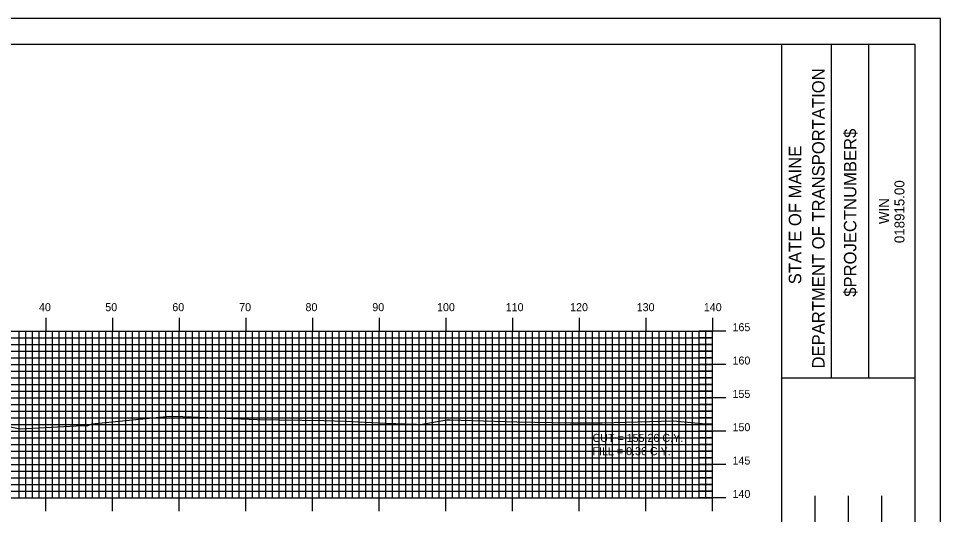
# Model space of a CAD drawing. Extents: x 861045 to 861388, y 364765 to 364985.
# Drawn here: x 861246.8 to 861385.1, y 364910.8 to 364985.2 of the extents above; entities that cross this region are included whole.
import ezdxf

# ---------------------------------------------------------------- set-up
doc = ezdxf.new("R2010")
doc.units = 0
for name, color, linetype in [('BORDER', 7, 'Continuous'), ('D_Text_Standard', 7, 'Continuous'), ('H_V ANNOTATION', 7, 'Continuous'), ('MAJOR', 7, 'Continuous'), ('MINOR', 7, 'Continuous'), ('PLOT BOUNDARY', 7, 'Continuous'), ('S_Roadway_Centerline', 7, 'Continuous')]:
    doc.layers.add(name, color=color, linetype=linetype)

msp = doc.modelspace()

# ---------------------------------------------------------------- linework, layer by layer
at = {"layer": 'BORDER'}
for p, q in [((861361.33, 364771.3), (861361.33, 364981.3)), ((861368.78, 364931.3), (861368.78, 364981.3)), ((861374.37, 364931.3), (861374.37, 364981.3)), ((861361.33, 364931.29), (861381.33, 364931.29)), ((861366.33, 364896.31), (861366.33, 364913.6)), ((861371.33, 364896.31), (861371.33, 364913.6)), ((861376.33, 364896.31), (861376.33, 364913.6))]:
    msp.add_line(p, q, dxfattribs=at)
msp.add_lwpolyline([(861061.33, 364771.3), (861381.33, 364771.3), (861381.33, 364981.3), (861061.33, 364981.3)], close=True, dxfattribs=at)
at = {"layer": 'MAJOR'}
for p, q in [((861250.93, 364940.31), (861250.93, 364938.3)), ((861260.93, 364940.31), (861260.93, 364938.3)), ((861270.93, 364940.31), (861270.93, 364938.3)), ((861280.93, 364940.31), (861280.93, 364938.3)), ((861290.93, 364940.31), (861290.93, 364938.3)), ((861300.93, 364940.31), (861300.93, 364938.3)), ((861310.93, 364940.31), (861310.93, 364938.3)), ((861320.93, 364940.31), (861320.93, 364938.3)), ((861330.93, 364940.31), (861330.93, 364938.3)), ((861340.93, 364940.31), (861340.93, 364938.3)), ((861350.93, 364940.31), (861350.93, 364938.3)), ((861070.93, 364938.3), (861350.93, 364938.3)), ((861070.93, 364938.3), (861350.93, 364938.3)), ((861070.93, 364938.3), (861350.93, 364938.3)), ((861250.93, 364913.3), (861250.93, 364938.3)), ((861250.93, 364913.3), (861250.93, 364938.3)), ((861260.93, 364913.3), (861260.93, 364938.3)), ((861260.93, 364913.3), (861260.93, 364938.3)), ((861270.93, 364913.3), (861270.93, 364938.3)), ((861270.93, 364913.3), (861270.93, 364938.3)), ((861280.93, 364913.3), (861280.93, 364938.3)), ((861280.93, 364913.3), (861280.93, 364938.3)), ((861290.93, 364913.3), (861290.93, 364938.3)), ((861290.93, 364913.3), (861290.93, 364938.3)), ((861300.93, 364913.3), (861300.93, 364938.3)), ((861300.93, 364913.3), (861300.93, 364938.3)), ((861310.93, 364913.3), (861310.93, 364938.3)), ((861310.93, 364913.3), (861310.93, 364938.3)), ((861320.93, 364913.3), (861320.93, 364938.3)), ((861320.93, 364913.3), (861320.93, 364938.3)), ((861330.93, 364913.3), (861330.93, 364938.3)), ((861330.93, 364913.3), (861330.93, 364938.3)), ((861340.93, 364913.3), (861340.93, 364938.3)), ((861340.93, 364913.3), (861340.93, 364938.3)), ((861352.93, 364938.3), (861348.92, 364938.3)), ((861350.93, 364913.3), (861350.93, 364938.3)), ((861350.93, 364913.3), (861350.93, 364938.3)), ((861350.93, 364913.3), (861350.93, 364938.3)), ((861070.93, 364933.3), (861350.93, 364933.3)), ((861070.93, 364933.3), (861350.93, 364933.3)), ((861352.93, 364933.3), (861348.92, 364933.3)), ((861070.93, 364928.3), (861350.93, 364928.3)), ((861070.93, 364928.3), (861350.93, 364928.3)), ((861352.93, 364928.3), (861348.92, 364928.3)), ((861070.93, 364923.3), (861350.93, 364923.3)), ((861070.93, 364923.3), (861350.93, 364923.3)), ((861352.93, 364923.3), (861348.92, 364923.3)), ((861070.93, 364918.3), (861350.93, 364918.3)), ((861070.93, 364918.3), (861350.93, 364918.3)), ((861352.93, 364918.3), (861348.92, 364918.3)), ((861070.93, 364913.3), (861350.93, 364913.3)), ((861070.93, 364913.3), (861350.93, 364913.3)), ((861070.93, 364913.3), (861350.93, 364913.3)), ((861250.93, 364911.3), (861250.93, 364913.3)), ((861260.93, 364911.3), (861260.93, 364913.3)), ((861270.93, 364911.3), (861270.93, 364913.3)), ((861280.93, 364911.3), (861280.93, 364913.3)), ((861290.93, 364911.3), (861290.93, 364913.3)), ((861300.93, 364911.3), (861300.93, 364913.3)), ((861310.93, 364911.3), (861310.93, 364913.3)), ((861320.93, 364911.3), (861320.93, 364913.3)), ((861330.93, 364911.3), (861330.93, 364913.3)), ((861340.93, 364911.3), (861340.93, 364913.3)), ((861352.93, 364913.3), (861348.92, 364913.3)), ((861350.93, 364911.3), (861350.93, 364913.3))]:
    msp.add_line(p, q, dxfattribs=at)
at = {"layer": 'MINOR'}
for p, q in [((861246.93, 364913.3), (861246.93, 364938.3)), ((861246.93, 364913.3), (861246.93, 364938.3)), ((861247.93, 364913.3), (861247.93, 364938.3)), ((861247.93, 364913.3), (861247.93, 364938.3)), ((861248.93, 364913.3), (861248.93, 364938.3)), ((861248.93, 364913.3), (861248.93, 364938.3)), ((861249.93, 364913.3), (861249.93, 364938.3)), ((861249.93, 364913.3), (861249.93, 364938.3)), ((861251.93, 364913.3), (861251.93, 364938.3)), ((861251.93, 364913.3), (861251.93, 364938.3)), ((861252.93, 364913.3), (861252.93, 364938.3)), ((861252.93, 364913.3), (861252.93, 364938.3)), ((861253.93, 364913.3), (861253.93, 364938.3)), ((861253.93, 364913.3), (861253.93, 364938.3)), ((861254.93, 364913.3), (861254.93, 364938.3)), ((861254.93, 364913.3), (861254.93, 364938.3)), ((861255.93, 364913.3), (861255.93, 364938.3)), ((861255.93, 364913.3), (861255.93, 364938.3)), ((861256.93, 364913.3), (861256.93, 364938.3)), ((861256.93, 364913.3), (861256.93, 364938.3)), ((861257.93, 364913.3), (861257.93, 364938.3)), ((861257.93, 364913.3), (861257.93, 364938.3)), ((861258.93, 364913.3), (861258.93, 364938.3)), ((861258.93, 364913.3), (861258.93, 364938.3)), ((861259.93, 364913.3), (861259.93, 364938.3)), ((861259.93, 364913.3), (861259.93, 364938.3)), ((861261.93, 364913.3), (861261.93, 364938.3)), ((861261.93, 364913.3), (861261.93, 364938.3)), ((861262.93, 364913.3), (861262.93, 364938.3)), ((861262.93, 364913.3), (861262.93, 364938.3)), ((861263.93, 364913.3), (861263.93, 364938.3)), ((861263.93, 364913.3), (861263.93, 364938.3)), ((861264.93, 364913.3), (861264.93, 364938.3)), ((861264.93, 364913.3), (861264.93, 364938.3)), ((861265.93, 364913.3), (861265.93, 364938.3)), ((861265.93, 364913.3), (861265.93, 364938.3)), ((861266.93, 364913.3), (861266.93, 364938.3)), ((861266.93, 364913.3), (861266.93, 364938.3)), ((861267.93, 364913.3), (861267.93, 364938.3)), ((861267.93, 364913.3), (861267.93, 364938.3)), ((861268.93, 364913.3), (861268.93, 364938.3)), ((861268.93, 364913.3), (861268.93, 364938.3)), ((861269.93, 364913.3), (861269.93, 364938.3)), ((861269.93, 364913.3), (861269.93, 364938.3)), ((861271.93, 364913.3), (861271.93, 364938.3)), ((861271.93, 364913.3), (861271.93, 364938.3)), ((861272.93, 364913.3), (861272.93, 364938.3)), ((861272.93, 364913.3), (861272.93, 364938.3)), ((861273.93, 364913.3), (861273.93, 364938.3)), ((861273.93, 364913.3), (861273.93, 364938.3)), ((861274.93, 364913.3), (861274.93, 364938.3)), ((861274.93, 364913.3), (861274.93, 364938.3)), ((861275.93, 364913.3), (861275.93, 364938.3)), ((861275.93, 364913.3), (861275.93, 364938.3)), ((861276.93, 364913.3), (861276.93, 364938.3)), ((861276.93, 364913.3), (861276.93, 364938.3)), ((861277.93, 364913.3), (861277.93, 364938.3)), ((861277.93, 364913.3), (861277.93, 364938.3)), ((861278.93, 364913.3), (861278.93, 364938.3)), ((861278.93, 364913.3), (861278.93, 364938.3)), ((861279.93, 364913.3), (861279.93, 364938.3)), ((861279.93, 364913.3), (861279.93, 364938.3)), ((861281.93, 364913.3), (861281.93, 364938.3)), ((861281.93, 364913.3), (861281.93, 364938.3)), ((861282.93, 364913.3), (861282.93, 364938.3)), ((861282.93, 364913.3), (861282.93, 364938.3)), ((861283.93, 364913.3), (861283.93, 364938.3)), ((861283.93, 364913.3), (861283.93, 364938.3)), ((861284.93, 364913.3), (861284.93, 364938.3)), ((861284.93, 364913.3), (861284.93, 364938.3)), ((861285.93, 364913.3), (861285.93, 364938.3)), ((861285.93, 364913.3), (861285.93, 364938.3)), ((861286.93, 364913.3), (861286.93, 364938.3)), ((861286.93, 364913.3), (861286.93, 364938.3)), ((861287.93, 364913.3), (861287.93, 364938.3)), ((861287.93, 364913.3), (861287.93, 364938.3)), ((861288.93, 364913.3), (861288.93, 364938.3)), ((861288.93, 364913.3), (861288.93, 364938.3)), ((861289.93, 364913.3), (861289.93, 364938.3)), ((861289.93, 364913.3), (861289.93, 364938.3)), ((861291.93, 364913.3), (861291.93, 364938.3)), ((861291.93, 364913.3), (861291.93, 364938.3)), ((861292.93, 364913.3), (861292.93, 364938.3)), ((861292.93, 364913.3), (861292.93, 364938.3)), ((861293.93, 364913.3), (861293.93, 364938.3)), ((861293.93, 364913.3), (861293.93, 364938.3)), ((861294.93, 364913.3), (861294.93, 364938.3)), ((861294.93, 364913.3), (861294.93, 364938.3)), ((861295.93, 364913.3), (861295.93, 364938.3)), ((861295.93, 364913.3), (861295.93, 364938.3)), ((861296.93, 364913.3), (861296.93, 364938.3)), ((861296.93, 364913.3), (861296.93, 364938.3)), ((861297.93, 364913.3), (861297.93, 364938.3)), ((861297.93, 364913.3), (861297.93, 364938.3)), ((861298.93, 364913.3), (861298.93, 364938.3)), ((861298.93, 364913.3), (861298.93, 364938.3)), ((861299.93, 364913.3), (861299.93, 364938.3)), ((861299.93, 364913.3), (861299.93, 364938.3)), ((861301.93, 364913.3), (861301.93, 364938.3)), ((861301.93, 364913.3), (861301.93, 364938.3)), ((861302.93, 364913.3), (861302.93, 364938.3)), ((861302.93, 364913.3), (861302.93, 364938.3)), ((861303.93, 364913.3), (861303.93, 364938.3)), ((861303.93, 364913.3), (861303.93, 364938.3)), ((861304.93, 364913.3), (861304.93, 364938.3)), ((861304.93, 364913.3), (861304.93, 364938.3)), ((861305.93, 364913.3), (861305.93, 364938.3)), ((861305.93, 364913.3), (861305.93, 364938.3)), ((861306.93, 364913.3), (861306.93, 364938.3)), ((861306.93, 364913.3), (861306.93, 364938.3)), ((861307.93, 364913.3), (861307.93, 364938.3)), ((861307.93, 364913.3), (861307.93, 364938.3)), ((861308.93, 364913.3), (861308.93, 364938.3)), ((861308.93, 364913.3), (861308.93, 364938.3)), ((861309.93, 364913.3), (861309.93, 364938.3)), ((861309.93, 364913.3), (861309.93, 364938.3)), ((861311.93, 364913.3), (861311.93, 364938.3)), ((861311.93, 364913.3), (861311.93, 364938.3)), ((861312.93, 364913.3), (861312.93, 364938.3)), ((861312.93, 364913.3), (861312.93, 364938.3)), ((861313.93, 364913.3), (861313.93, 364938.3)), ((861313.93, 364913.3), (861313.93, 364938.3)), ((861314.93, 364913.3), (861314.93, 364938.3)), ((861314.93, 364913.3), (861314.93, 364938.3)), ((861315.93, 364913.3), (861315.93, 364938.3)), ((861315.93, 364913.3), (861315.93, 364938.3)), ((861316.93, 364913.3), (861316.93, 364938.3)), ((861316.93, 364913.3), (861316.93, 364938.3)), ((861317.93, 364913.3), (861317.93, 364938.3)), ((861317.93, 364913.3), (861317.93, 364938.3)), ((861318.93, 364913.3), (861318.93, 364938.3)), ((861318.93, 364913.3), (861318.93, 364938.3)), ((861319.93, 364913.3), (861319.93, 364938.3)), ((861319.93, 364913.3), (861319.93, 364938.3)), ((861321.93, 364913.3), (861321.93, 364938.3)), ((861321.93, 364913.3), (861321.93, 364938.3)), ((861322.93, 364913.3), (861322.93, 364938.3)), ((861322.93, 364913.3), (861322.93, 364938.3)), ((861323.93, 364913.3), (861323.93, 364938.3)), ((861323.93, 364913.3), (861323.93, 364938.3)), ((861324.93, 364913.3), (861324.93, 364938.3)), ((861324.93, 364913.3), (861324.93, 364938.3)), ((861325.93, 364913.3), (861325.93, 364938.3)), ((861325.93, 364913.3), (861325.93, 364938.3)), ((861326.93, 364913.3), (861326.93, 364938.3)), ((861326.93, 364913.3), (861326.93, 364938.3)), ((861327.93, 364913.3), (861327.93, 364938.3)), ((861327.93, 364913.3), (861327.93, 364938.3)), ((861328.93, 364913.3), (861328.93, 364938.3)), ((861328.93, 364913.3), (861328.93, 364938.3)), ((861329.93, 364913.3), (861329.93, 364938.3)), ((861329.93, 364913.3), (861329.93, 364938.3)), ((861331.93, 364913.3), (861331.93, 364938.3)), ((861331.93, 364913.3), (861331.93, 364938.3)), ((861332.93, 364913.3), (861332.93, 364938.3)), ((861332.93, 364913.3), (861332.93, 364938.3)), ((861333.93, 364913.3), (861333.93, 364938.3)), ((861333.93, 364913.3), (861333.93, 364938.3)), ((861334.93, 364913.3), (861334.93, 364938.3)), ((861334.93, 364913.3), (861334.93, 364938.3)), ((861335.93, 364913.3), (861335.93, 364938.3)), ((861335.93, 364913.3), (861335.93, 364938.3)), ((861336.93, 364913.3), (861336.93, 364938.3)), ((861336.93, 364913.3), (861336.93, 364938.3)), ((861337.93, 364913.3), (861337.93, 364938.3)), ((861337.93, 364913.3), (861337.93, 364938.3)), ((861338.93, 364913.3), (861338.93, 364938.3)), ((861338.93, 364913.3), (861338.93, 364938.3)), ((861339.93, 364913.3), (861339.93, 364938.3)), ((861339.93, 364913.3), (861339.93, 364938.3)), ((861341.93, 364913.3), (861341.93, 364938.3)), ((861341.93, 364913.3), (861341.93, 364938.3)), ((861342.93, 364913.3), (861342.93, 364938.3)), ((861342.93, 364913.3), (861342.93, 364938.3)), ((861343.93, 364913.3), (861343.93, 364938.3)), ((861343.93, 364913.3), (861343.93, 364938.3)), ((861344.93, 364913.3), (861344.93, 364938.3)), ((861344.93, 364913.3), (861344.93, 364938.3)), ((861345.93, 364913.3), (861345.93, 364938.3)), ((861345.93, 364913.3), (861345.93, 364938.3)), ((861346.93, 364913.3), (861346.93, 364938.3)), ((861346.93, 364913.3), (861346.93, 364938.3)), ((861347.93, 364913.3), (861347.93, 364938.3)), ((861347.93, 364913.3), (861347.93, 364938.3)), ((861348.93, 364913.3), (861348.93, 364938.3)), ((861348.93, 364913.3), (861348.93, 364938.3)), ((861349.93, 364913.3), (861349.93, 364938.3)), ((861349.93, 364913.3), (861349.93, 364938.3)), ((861070.93, 364937.3), (861350.93, 364937.3)), ((861070.93, 364937.3), (861350.93, 364937.3)), ((861070.93, 364936.3), (861350.93, 364936.3)), ((861070.93, 364936.3), (861350.93, 364936.3)), ((861350.93, 364937.3), (861348.92, 364937.3)), ((861350.93, 364936.3), (861348.92, 364936.3)), ((861070.93, 364935.3), (861350.93, 364935.3)), ((861070.93, 364935.3), (861350.93, 364935.3)), ((861350.93, 364935.3), (861348.92, 364935.3)), ((861070.93, 364934.3), (861350.93, 364934.3)), ((861070.93, 364934.3), (861350.93, 364934.3)), ((861350.93, 364934.3), (861348.92, 364934.3)), ((861070.93, 364932.3), (861350.93, 364932.3)), ((861070.93, 364932.3), (861350.93, 364932.3)), ((861350.93, 364932.3), (861348.92, 364932.3)), ((861070.93, 364931.3), (861350.93, 364931.3)), ((861070.93, 364931.3), (861350.93, 364931.3)), ((861350.93, 364931.3), (861348.92, 364931.3)), ((861070.93, 364930.3), (861350.93, 364930.3)), ((861070.93, 364930.3), (861350.93, 364930.3)), ((861070.93, 364929.3), (861350.93, 364929.3)), ((861070.93, 364929.3), (861350.93, 364929.3)), ((861350.93, 364930.3), (861348.92, 364930.3)), ((861350.93, 364929.3), (861348.92, 364929.3)), ((861070.93, 364927.3), (861350.93, 364927.3)), ((861070.93, 364927.3), (861350.93, 364927.3)), ((861350.93, 364927.3), (861348.92, 364927.3)), ((861070.93, 364926.3), (861350.93, 364926.3)), ((861070.93, 364926.3), (861350.93, 364926.3)), ((861070.93, 364925.3), (861350.93, 364925.3)), ((861070.93, 364925.3), (861350.93, 364925.3)), ((861350.93, 364926.3), (861348.92, 364926.3)), ((861350.93, 364925.3), (861348.92, 364925.3)), ((861070.93, 364924.3), (861350.93, 364924.3)), ((861070.93, 364924.3), (861350.93, 364924.3)), ((861350.93, 364924.3), (861348.92, 364924.3)), ((861070.93, 364922.3), (861350.93, 364922.3)), ((861070.93, 364922.3), (861350.93, 364922.3)), ((861070.93, 364921.3), (861350.93, 364921.3)), ((861070.93, 364921.3), (861350.93, 364921.3)), ((861350.93, 364922.3), (861348.92, 364922.3)), ((861350.93, 364921.3), (861348.92, 364921.3)), ((861070.93, 364920.3), (861350.93, 364920.3)), ((861070.93, 364920.3), (861350.93, 364920.3)), ((861350.93, 364920.3), (861348.92, 364920.3)), ((861070.93, 364919.3), (861350.93, 364919.3)), ((861070.93, 364919.3), (861350.93, 364919.3)), ((861350.93, 364919.3), (861348.92, 364919.3)), ((861070.93, 364917.3), (861350.93, 364917.3)), ((861070.93, 364917.3), (861350.93, 364917.3)), ((861350.93, 364917.3), (861348.92, 364917.3)), ((861070.93, 364916.3), (861350.93, 364916.3)), ((861070.93, 364916.3), (861350.93, 364916.3)), ((861350.93, 364916.3), (861348.92, 364916.3)), ((861070.93, 364915.3), (861350.93, 364915.3)), ((861070.93, 364915.3), (861350.93, 364915.3)), ((861070.93, 364914.3), (861350.93, 364914.3)), ((861070.93, 364914.3), (861350.93, 364914.3)), ((861350.93, 364915.3), (861348.92, 364915.3)), ((861350.93, 364914.3), (861348.92, 364914.3))]:
    msp.add_line(p, q, dxfattribs=at)
at = {"layer": 'PLOT BOUNDARY'}
msp.add_lwpolyline([(861045.14, 364765.18), (861385.14, 364765.18), (861385.14, 364985.18), (861045.14, 364985.18)], close=True, dxfattribs=at)
at = {"layer": 'S_Roadway_Centerline'}
msp.add_lwpolyline([(861243.06, 364924.46), (861247.09, 364923.65), (861256.42, 364924.17), (861257.12, 364924.17), (861257.15, 364924.1), (861257.81, 364924.41), (861269.53, 364925.54), (861271.47, 364925.52), (861282.66, 364925.04), (861292.62, 364924.9), (861295.85, 364924.8), (861301.87, 364924.51), (861306.54, 364924.37), (861307.08, 364924.31), (861310.76, 364924.95), (861311.13, 364925.02), (861311.18, 364925.02), (861311.6, 364925.01), (861321.56, 364924.72), (861329.63, 364924.57), (861329.86, 364924.54), (861334.39, 364924.54), (861345.04, 364924.85), (861349.4, 364924.46), (861350.93, 364924.4)], dxfattribs=at)

# ---------------------------------------------------------------- texts
at = {"layer": 'BORDER'}
for s, height, p in [('DEPARTMENT OF TRANSPORTATION', 1.8635, (861367.74, 364932.71)), ('$PROJECTNUMBER$', 1.8635, (861372.51, 364943.46)), ('STATE OF MAINE', 1.8635, (861364.24, 364945.33)), ('018915.00', 1.491, (861379.72, 364951.5)), ('WIN', 1.491, (861377.4, 364954.36))]:
    msp.add_text(s, height=height, rotation=90, dxfattribs=at).set_placement(p)
at = {"layer": 'D_Text_Standard'}
for s, p in [('CUT = 155.26 C.Y.', (861332.93, 364921.7)), ('FILL = 0.36 C.Y.', (861332.93, 364919.71))]:
    msp.add_text(s, height=1.2, dxfattribs=at).set_placement(p)
at = {"layer": 'H_V ANNOTATION'}
for s, p in [('40', (861249.9, 364941.3)), ('50', (861259.85, 364941.3)), ('60', (861269.9, 364941.3)), ('70', (861279.93, 364941.3)), ('80', (861289.88, 364941.3)), ('90', (861299.9, 364941.3)), ('100', (861309.61, 364941.3)), ('110', (861319.91, 364941.3)), ('120', (861329.57, 364941.3)), ('130', (861339.56, 364941.3)), ('140', (861349.63, 364941.3)), ('165', (861353.93, 364938.3)), ('160', (861353.93, 364933.3)), ('155', (861353.93, 364928.3)), ('150', (861353.93, 364923.3)), ('145', (861353.93, 364918.3)), ('140', (861353.93, 364913.3))]:
    msp.add_text(s, height=1.2, dxfattribs=at).set_placement(p)

doc.saveas('drawing.dxf')
